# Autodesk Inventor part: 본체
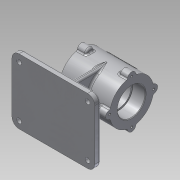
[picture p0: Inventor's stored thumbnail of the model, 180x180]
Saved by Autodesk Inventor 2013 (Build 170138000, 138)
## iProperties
Created: 2015-12
Part Number: 본체
Material: 알루미늄 6061
Document SubType Name: Modeling
Designer: Administrator
Density: 2.71 g/cm^3
Mass: 1167.11 g
Surface Area: 817.28 cm^2
Volume: 430.667 cm^3
Author: Administrator
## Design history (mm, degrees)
sketch "스케치1"
  geometry: L1 (-70, 55)-(70, 55); L2 (70, 55)-(70, -55); L3 (70, -55)-(-70, -55); L4 (-70, -55)-(-70, 55); 3 further points
  constraints: 8 end point, 2 midpoint, 2 parallel, 1 horizontal, 1 horizontal alignment, 1 perpendicular, 1 vertical alignment
extrude "돌출1" new body sketch "스케치1" distance "d3" = 10; taper "d4" = 0 deg
node "작업 평면1"
sketch "스케치2"
  geometry: L1 (0, 0)-(110, 0) reference; C1 r 37 at (55, 80); 1 further point
  constraints: 1 centre point
extrude "돌출2" join sketch "스케치2" distance "d8" = 85; taper "d9" = 0 deg
sketch "스케치3"
  geometry: 2 further points
hole "구멍1" sketch "스케치3" at (0, 0) diameter "d10" = 42; stored, may be unused: countersink angle "d14" = 90 deg, drill point angle "d16" = 0 deg; dims "d11" = 6, "d12" = 47, "d13" = 22, "d15" = 8
sketch "스케치4"
  geometry: C1 r 37 at (0, 0) reference; C2 r 23.5 at (0, 0); 1 further point
  constraints: 1 centre point, 1 coincident
  dimensions: "d17" = 47 diameter of C2
extrude "돌출3" cut sketch "스케치4" distance "d18" = 22; taper "d19" = 0 deg
sketch "스케치5"
  geometry: L1 (-70, 55)-(70, 55) reference; L2 (6, 37)-(14, 37); L3 (14, 37)-(14, -37); L4 (14, -37)-(6, -37); L5 (6, -37)-(6, 37); L6 (-70, -55)-(-70, 55) reference; 2 further points
  constraints: 8 end point, 2 parallel, 1 horizontal, 1 horizontal alignment, 1 midpoint, 1 perpendicular
extrude "돌출4" join sketch "스케치5" stored distance "d29" = 0; taper "d30" = 0 deg
sketch "스케치8"
  geometry: L1 (70, 10)-(-70, 10) reference; L2 (-32.5, 117)-(52.5, 117) reference; L3 (-32.5, 43)-(52.5, 43) reference; L4 (-15, 10)-(-10.948, 43); L5 (35, 10)-(30.948, 43); 1 further point
  constraints: 4 end point, 2 point on line
feature "리브1" sketch "스케치8" dims "d40" = 1, "d41" = 12, "d42" = 0, "d43" = 0, "d44" = 1, "d45" = 1
sketch "스케치9"
  geometry: L1 (-32.5, 43)-(52.5, 43) reference; L2 (70, 10)-(-70, 10) reference; L3 (30.948, 43)-(35, 10); L4 (-32.5, 117)-(52.5, 117) reference; 1 further point
  constraints: 2 end point, 2 point on line
feature "리브2" sketch "스케치9" dims "d50" = 1, "d51" = 12, "d52" = 0, "d53" = 0, "d54" = 1, "d55" = 1
sketch "스케치10"
  geometry: A1 r 7 centre (0, 37) between (6.969, 36.338) and (-6.969, 36.338); A2 r 7 centre (-37, 0) between (-36.338, 6.969) and (-36.338, -6.969); A3 r 7 centre (0, -37) between (-6.969, -36.338) and (6.969, -36.338); A4 r 7 centre (37, 0) between (36.338, -6.969) and (36.338, 6.969); 2 further points
  constraints: 8 point on circle, 4 centre point, 10 other
  dimensions: "d56" = 14 diameter of A1
extrude "돌출5" join sketch "스케치10" distance "d60" = 15; taper "d61" = 0 deg
sketch "스케치11"
  geometry: C1 r 23.5 at (55, 80) reference; A1 r 37 centre (55, 80) between (91.338, 86.969) and (61.969, 116.338) reference; A2 r 7 centre (55, 117) between (61.969, 116.338) and (48.031, 116.338) reference; A3 r 37 centre (55, 80) between (48.031, 116.338) and (18.662, 86.969) reference; A4 r 7 centre (18, 80) between (18.662, 86.969) and (18.662, 73.031) reference; A5 r 37 centre (55, 80) between (18.662, 73.031) and (48.031, 43.662) reference; A6 r 7 centre (55, 43) between (48.031, 43.662) and (61.969, 43.662) reference; A7 r 37 centre (55, 80) between (61.969, 43.662) and (91.338, 73.031) reference; A8 r 7 centre (92, 80) between (91.338, 73.031) and (91.338, 86.969) reference; 2 further points
  constraints: 1 coincident
hole "구멍2" sketch "스케치11" at (55, 117) diameter "d62" = 3.459; stored, may be unused: countersink angle "d66" = 90 deg, drill point angle "d68" = 118 deg; dims "d63" = 9, "d64" = 47, "d65" = 22, "d67" = 11
sketch "스케치12"
  geometry: C1 r 23.5 at (0, 0) reference; A1 r 7 centre (0, 37) between (6.969, 36.338) and (-6.969, 36.338); A2 r 7 centre (-37, 0) between (-36.338, 6.969) and (-36.338, -6.969); A3 r 7 centre (0, -37) between (-6.969, -36.338) and (6.969, -36.338); A4 r 7 centre (37, 0) between (36.338, -6.969) and (36.338, 6.969); 2 further points
  constraints: 8 point on circle, 4 centre point, 10 other
extrude "돌출6" join sketch "스케치12" distance "d76" = 15; taper "d77" = 0 deg
sketch "스케치13"
  geometry: C1 r 23.5 at (-55, 80) reference; A1 r 37 centre (-55, 80) between (-91.338, 73.031) and (-61.969, 43.662) reference; A2 r 7 centre (-55, 43) between (-61.969, 43.662) and (-48.031, 43.662) reference; A3 r 37 centre (-55, 80) between (-48.031, 43.662) and (-18.662, 73.031) reference; A4 r 7 centre (-18, 80) between (-18.662, 73.031) and (-18.662, 86.969) reference; A5 r 37 centre (-55, 80) between (-18.662, 86.969) and (-48.031, 116.338) reference; A6 r 7 centre (-55, 117) between (-48.031, 116.338) and (-61.969, 116.338) reference; A7 r 37 centre (-55, 80) between (-61.969, 116.338) and (-91.338, 86.969) reference; A8 r 7 centre (-92, 80) between (-91.338, 86.969) and (-91.338, 73.031) reference; 2 further points
  constraints: 1 coincident
hole "구멍3" sketch "스케치13" at (-55, 117) diameter "d78" = 3.459; stored, may be unused: countersink angle "d82" = 90 deg, drill point angle "d84" = 118 deg; dims "d79" = 9, "d80" = 47, "d81" = 22, "d83" = 11
sketch "스케치14"
  geometry: L1 (70, 55)-(-70, 55) reference; C1 r 4 at (-58, 43); 1 further point
  constraints: 1 centre point
  dimensions: "d88" = 8 diameter of C1
extrude "돌출7" cut sketch "스케치14" distance "d91" = 20; taper "d92" = 0 deg
node "작업 평면2"
sketch "스케치16"
  geometry: L1 (55, 80)-(81.163, 106.163); A1 r 37 centre (55, 80) between (91.338, 86.969) and (61.969, 116.338) reference; 1 further point
  constraints: 2 end point, 1 point on circle
node "작업 평면3"
sketch "스케치17"
  geometry: L1 (42.5, 20.767)-(42.5, -20.767) reference; 2 further points
  constraints: 1 other
feature "엠보싱1" sketch "스케치17" dims "d96" = 0.5, "d97" = 0
chamfer "모따기1" distance "d98" = 1; stored, may be unused: second distance "d99" = 2, angle "d100" = 45 deg
fillet "모깎기1" dims "d101" = 12, "d102" = 3, "d103" = 0.3
fillet "모깎기2" dims "d104" = 3
node "솔리드1"
pattern_circular "원형 패턴1" dims angle "d70" = 360 deg
pattern_circular "원형 패턴2" dims angle "d86" = 360 deg
mirror "대칭1"
mirror "대칭2"
node "투영된 루프1"
node "투영된 루프2"
node "투영된 루프3"
other parameters: "d5" = -37.5, "d93" = -42.5
